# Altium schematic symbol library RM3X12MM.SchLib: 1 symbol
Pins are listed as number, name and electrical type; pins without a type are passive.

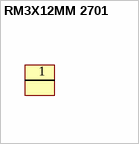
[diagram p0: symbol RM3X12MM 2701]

## RM3X12MM 2701
designator H?
MACHINE SCREW PAN PHILLIPS M3; Manufacturer: Used in BOM report; SymbolVersion: 2014 - 10 - 22; SymbolCreator: A0412036; CompType: Used in some BOM reports.  Useful for finding later.; U/M: EA
footprint M 3X0_5 SCREW (M 3X0.5 SCREW)
footprint M 3X0_5 WITH SPRING (M 3X0.5 SCREW WITH ATS-PPS-06 SPRING)
pins: 1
